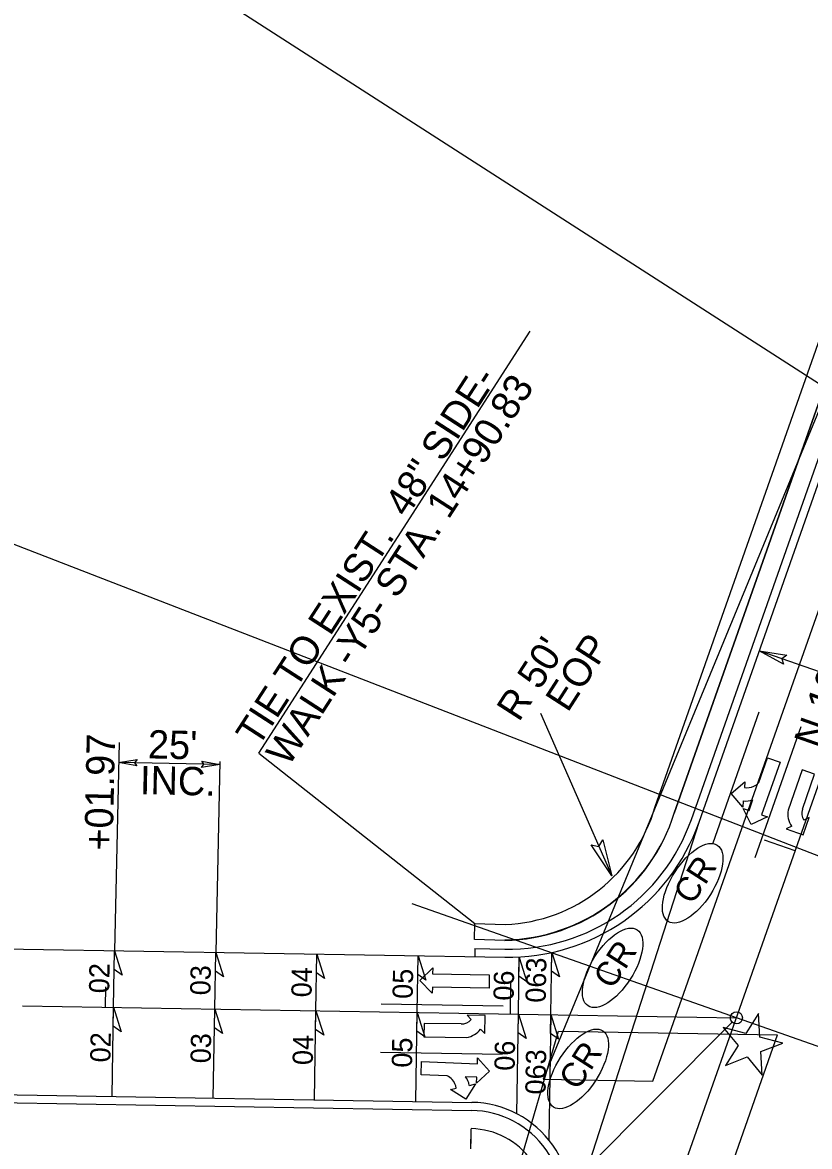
# Model space of a CAD drawing. Extents: x 1974386 to 1979988, y 776712 to 784860.
# Drawn here: x 1977201.1 to 1977395.6, y 780817.6 to 781095.4 of the extents above; entities that cross this region are included whole.
import ezdxf

# ---------------------------------------------------------------- set-up
doc = ezdxf.new("R2010")
doc.units = 0
for name, color, linetype in [('Prop Conc 2ft 6in Curb and Gutter', 7, 'Continuous'), ('Prop Conc 4in Sidewalk', 7, 'Continuous'), ('Prop Conc 5in Monolithic Keyed In Island', 7, 'Continuous'), ('Prop Dimension', 7, 'Continuous'), ('Prop Dimension Text', 7, 'Continuous'), ('Prop EOT', 7, 'Continuous'), ('Prop Horizontal Alignment', 7, 'Continuous'), ('Prop Horizontal Alignment Direction Label', 7, 'Continuous'), ('Prop Horizontal Alignment Station Label', 7, 'Continuous'), ('Prop Horizontal Alignment Tick Large', 7, 'Continuous'), ('Prop Horizontal Alignment Tick Small', 7, 'Continuous'), ('Prop Lane Arrow CELL', 7, 'Continuous'), ('Prop Lane Lines', 7, 'Continuous'), ('Prop RDY Traffic Signal CELL', 7, 'Continuous'), ('Prop Superelevation  Arrow CELL', 7, 'Continuous'), ('Prop Superelevation Label', 7, 'Continuous'), ('Prop Terminator CELL', 7, 'Continuous'), ('Prop WCC CELL', 7, 'Continuous'), ('Scratch_Level_1', 7, 'Continuous'), ('Scratch_Level_2', 7, 'Continuous'), ('Scratch_Level_3', 7, 'Continuous'), ('Sheet Layout Plan Border', 7, 'Continuous')]:
    doc.layers.add(name, color=color, linetype=linetype)

msp = doc.modelspace()

# ---------------------------------------------------------------- linework, layer by layer
at = {"layer": 'Prop Conc 2ft 6in Curb and Gutter'}
for p, q in [((1977366.39, 780898.48), (1977431.87, 781084.7)), ((1977312.89, 780866.54), (1977312.86, 780864.54)), ((1977312.89, 780866.54), (1977320.3, 780866.41)), ((1977159.54, 780829.11), (1977312.1, 780826.54))]:
    msp.add_line(p, q, dxfattribs=at)
for centre, radius, start, end in [((1977321.11, 780914.4), 48, 269.0355, 340.6265), ((1977311.71, 780803.55), 23, 341.3426, 89.0355)]:
    msp.add_arc(centre, radius, start, end, dxfattribs=at)
at = {"layer": 'Prop Conc 4in Sidewalk'}
for p, q in [((1977357.43, 780901.63), (1977422.91, 781087.85)), ((1977357.43, 780901.63), (1977422.91, 781087.85)), ((1977362.15, 780899.97), (1977427.63, 781086.19)), ((1977427.63, 781086.19), (1977362.15, 780899.97)), ((1977312.81, 780868.8), (1977312.88, 780872.74)), ((1977312.88, 780872.74), (1977320.41, 780872.49)), ((1977320.34, 780868.55), (1977312.81, 780868.8)), ((1977311.94, 780817.04), (1977312.02, 780822.04)), ((1977311.98, 780819.54), (1977312.02, 780822.04)), ((1977311.94, 780817.04), (1977311.98, 780819.54))]:
    msp.add_line(p, q, dxfattribs=at)
for centre, radius, start, end in [((1977319.57, 780913.33), 44.63, 270.9928, 342.5837), ((1977319.46, 780913.25), 44.71, 271.1306, 342.7215), ((1977318.71, 780912.73), 40.28, 272.4111, 344.002), ((1977311.71, 780803.55), 18.5, 341.3426, 89.0355)]:
    msp.add_arc(centre, radius, start, end, dxfattribs=at)
at = {"layer": 'Prop Conc 5in Monolithic Keyed In Island'}
msp.add_line((1977297.32, 780877.65), (1977457.7, 780821.25), dxfattribs=at)
at = {"layer": 'Prop Dimension'}
for p, q in [((1977259.55, 780914.86), (1977326.6, 781019.14)), ((1977441.18, 780919.75), (1977383.17, 780940.15)), ((1977329.14, 780924.69), (1977346.72, 780884.53)), ((1977225, 780917.45), (1977223.89, 780866.03)), ((1977259.55, 780914.86), (1977312.88, 780872.74)), ((1977249.89, 780912), (1977224.9, 780912.54)), ((1977249.91, 780912.77), (1977248.89, 780865.61))]:
    msp.add_line(p, q, dxfattribs=at)
at = {"layer": 'Prop EOT'}
for p, q in [((1977368.28, 780897.82), (1977433.76, 781084.03)), ((1977009.95, 780869.54), (1977201.38, 780866.41)), ((1977201.38, 780866.41), (1977320.27, 780864.41)), ((1977159.58, 780831.11), (1977312.13, 780828.54))]:
    msp.add_line(p, q, dxfattribs=at)
for centre, radius, start, end in [((1977321.11, 780914.4), 50, 269.0355, 340.6265), ((1977311.71, 780803.55), 25, 341.3426, 89.0355)]:
    msp.add_arc(centre, radius, start, end, dxfattribs=at)
at = {"layer": 'Prop Horizontal Alignment'}
for p, q in [((1977307.82, 780651.27), (1977457.11, 781075.82)), ((1977201.14, 780852.41), (1977377.51, 780849.45)), ((1977201.14, 780852.41), (1977377.51, 780849.45))]:
    msp.add_line(p, q, dxfattribs=at)
at = {"layer": 'Prop Horizontal Alignment Station Label'}
msp.add_line((1977376.45, 780848.38), (1977216.45, 780687.69), dxfattribs=at)
msp.add_circle((1977377.51, 780849.45), 1.5, dxfattribs=at)
msp.add_circle((1977377.51, 780849.45), 1.5, dxfattribs=at)
at = {"layer": 'Prop Horizontal Alignment Tick Large'}
for p, q in [((1977392.01, 780890.69), (1977384.46, 780893.35)), ((1977321.67, 780850.39), (1977321.81, 780858.38))]:
    msp.add_line(p, q, dxfattribs=at)
at = {"layer": 'Prop Horizontal Alignment Tick Small'}
msp.add_line((1977221.69, 780852.07), (1977221.77, 780857.07), dxfattribs=at)
at = {"layer": 'Prop Lane Arrow CELL'}
for p, q in [((1977383.05, 780907.62), (1977385.18, 780913.71)), ((1977385.18, 780913.71), (1977388.3, 780912.62)), ((1977388.3, 780912.62), (1977383.74, 780899.59)), ((1977393.72, 780910.72), (1977390.3, 780900.73)), ((1977396.84, 780909.65), (1977393.72, 780910.72)), ((1977376.21, 780904.87), (1977379.56, 780907.78)), ((1977379.56, 780907.78), (1977379.48, 780906.33)), ((1977393.88, 780900.99), (1977396.84, 780909.65)), ((1977379.12, 780901.52), (1977376.21, 780904.87)), ((1977379.22, 780903.02), (1977379.12, 780901.52)), ((1977380.63, 780900.68), (1977381.57, 780903.37)), ((1977381.16, 780897.21), (1977379.21, 780901.17)), ((1977379.21, 780901.17), (1977380.63, 780900.68)), ((1977383.74, 780899.59), (1977385.16, 780899.1)), ((1977385.16, 780899.1), (1977381.16, 780897.21)), ((1977391.17, 780896.79), (1977389.84, 780896.14)), ((1977393.98, 780894.66), (1977395.49, 780898.91)), ((1977395.49, 780898.91), (1977394.16, 780898.25)), ((1977389.84, 780896.14), (1977393.98, 780894.66)), ((1977299.29, 780858.66), (1977302.5, 780861.79)), ((1977302.5, 780861.79), (1977302.47, 780860.3)), ((1977302.38, 780855.5), (1977299.29, 780858.66)), ((1977302.47, 780860.3), (1977316.47, 780860.03)), ((1977316.47, 780860.03), (1977316.41, 780856.73)), ((1977302.41, 780857), (1977302.38, 780855.5)), ((1977316.41, 780856.73), (1977302.41, 780857)), ((1977315.47, 780850), (1977310.97, 780850.1)), ((1977310.97, 780850.1), (1977312.01, 780849.04)), ((1977315.37, 780845.6), (1977315.47, 780850)), ((1977300.34, 780848.02), (1977300.31, 780844.72)), ((1977309.49, 780847.92), (1977300.34, 780848.02)), ((1977314.33, 780846.66), (1977315.37, 780845.6)), ((1977300.31, 780844.72), (1977310.86, 780844.6)), ((1977299.6, 780835.35), (1977299.74, 780838.65)), ((1977299.74, 780838.65), (1977313.53, 780838.07)), ((1977313.53, 780838.07), (1977313.59, 780839.57)), ((1977313.59, 780839.57), (1977316.55, 780836.29)), ((1977316.55, 780836.29), (1977313.33, 780833.27)), ((1977306.04, 780835.08), (1977299.6, 780835.35)), ((1977313.39, 780834.77), (1977310.54, 780834.89)), ((1977313.02, 780833.09), (1977310.66, 780829.33)), ((1977311.55, 780832.75), (1977313.02, 780833.09)), ((1977313.33, 780833.27), (1977313.39, 780834.77)), ((1977306.9, 780831.69), (1977308.32, 780832.03)), ((1977310.66, 780829.33), (1977306.9, 780831.69))]:
    msp.add_line(p, q, dxfattribs=at)
for centre, radius, start, end in [((1977380.06, 780910.72), 4.43, 262.4428, 293.2964), ((1977380.96, 780909.03), 2.52, 289.8063, 326.1183), ((1977379.82, 780907.43), 4.43, 262.324, 293.2026), ((1977395.45, 780899.81), 5.25, 169.7805, 215.0922), ((1977396.96, 780899.93), 3.27, 161.1044, 210.7626), ((1977309.54, 780851.18), 3.27, 269.3608, 319.019), ((1977310.12, 780849.79), 5.25, 278.0369, 323.3486), ((1977305.3, 780832.66), 2.52, 36.676, 72.988), ((1977303.94, 780831.31), 4.43, 9.3125, 40.1661), ((1977307.16, 780832.04), 4.43, 9.1937, 40.0723)]:
    msp.add_arc(centre, radius, start, end, dxfattribs=at)
at = {"layer": 'Prop Lane Lines'}
for p, q in [((1977371.78, 780892.7), (1977383.16, 780925.07)), ((1977382.16, 780889.06), (1977393.54, 780921.42)), ((1977289.77, 780852.92), (1977319.93, 780852.41)), ((1977289.57, 780840.92), (1977319.73, 780840.42))]:
    msp.add_line(p, q, dxfattribs=at)
at = {"layer": 'Prop RDY Traffic Signal CELL'}
msp.add_lwpolyline([(1977377.92, 780842.57), (1977374.78, 780837.69), (1977380.19, 780839.79), (1977383.87, 780835.29), (1977383.54, 780841.1), (1977388.96, 780843.21), (1977383.34, 780844.68), (1977383.01, 780850.48), (1977379.86, 780845.6), (1977374.24, 780847.07), (1977377.92, 780842.57)], dxfattribs=at)
at = {"layer": 'Prop Superelevation  Arrow CELL'}
for p, q in [((1977223.66, 780852.04), (1977223.89, 780866.03)), ((1977248.65, 780851.61), (1977248.89, 780865.61)), ((1977273.65, 780851.19), (1977273.89, 780865.19)), ((1977298.65, 780850.77), (1977298.88, 780864.77)), ((1977323.64, 780850.35), (1977323.88, 780864.35)), ((1977331.67, 780850.22), (1977331.93, 780865.59)), ((1977223.29, 780830.04), (1977223.66, 780852.04)), ((1977248.28, 780829.62), (1977248.65, 780851.61)), ((1977273.28, 780829.2), (1977273.65, 780851.19)), ((1977298.28, 780828.78), (1977298.65, 780850.77)), ((1977323.23, 780825.73), (1977323.64, 780850.35)), ((1977331.67, 780850.22), (1977331.15, 780819.26))]:
    msp.add_line(p, q, dxfattribs=at)
for points in [[(1977223.89, 780866.03), (1977225.79, 780860), (1977223.82, 780861.41)], [(1977248.89, 780865.61), (1977250.79, 780859.58), (1977248.81, 780860.99)], [(1977273.89, 780865.19), (1977275.79, 780859.16), (1977273.81, 780860.57)], [(1977298.88, 780864.77), (1977300.78, 780858.74), (1977298.81, 780860.15)], [(1977323.88, 780864.35), (1977325.78, 780858.32), (1977323.8, 780859.73)], [(1977331.93, 780865.59), (1977333.83, 780859.56), (1977331.85, 780860.96)], [(1977223.66, 780852.04), (1977225.56, 780846), (1977223.58, 780847.41)], [(1977248.65, 780851.61), (1977250.55, 780845.58), (1977248.58, 780846.99)], [(1977273.65, 780851.19), (1977275.55, 780845.16), (1977273.57, 780846.57)], [(1977298.65, 780850.77), (1977300.55, 780844.74), (1977298.57, 780846.15)], [(1977323.64, 780850.35), (1977325.54, 780844.32), (1977323.57, 780845.73)], [(1977331.67, 780850.22), (1977333.57, 780844.18), (1977331.6, 780845.59)]]:
    msp.add_lwpolyline(points, close=True, dxfattribs=at)
at = {"layer": 'Prop Terminator CELL'}
for points in [[(1977389.15, 780936.82), (1977383.17, 780940.15), (1977389.97, 780939.03), (1977388.76, 780938.19)], [(1977229.38, 780911.67), (1977224.9, 780912.54), (1977229.44, 780913.24), (1977228.85, 780912.45)], [(1977245.41, 780912.87), (1977249.89, 780912), (1977245.35, 780911.3), (1977245.94, 780912.08)], [(1977344.53, 780893.4), (1977346.72, 780884.53), (1977341.63, 780892.18), (1977343.55, 780891.77)]]:
    msp.add_lwpolyline(points, close=True, dxfattribs=at)
at = {"layer": 'Prop WCC CELL'}
for centre in [(1977366.71, 780882.7), (1977346.93, 780861.79), (1977338.42, 780836.82)]:
    msp.add_ellipse(centre, major_axis=(6.07, 9.43), ratio=0.462467, dxfattribs=at)
at = {"layer": 'Scratch_Level_1'}
for p, q in [((1977516.04, 781286.37), (1977329.74, 780834.25)), ((1977356.9, 780833.79), (1977516.04, 781286.37)), ((1977329.74, 780834.25), (1977356.9, 780833.79))]:
    msp.add_line(p, q, dxfattribs=at)
at = {"layer": 'Scratch_Level_2'}
for p, q in [((1977203.85, 780401.24), (1977333.59, 780846.18)), ((1977318.2, 780647.62), (1977387.7, 780845.27)), ((1977333.59, 780846.18), (1977387.7, 780845.27))]:
    msp.add_line(p, q, dxfattribs=at)
at = {"layer": 'Scratch_Level_3'}
msp.add_line((1977335.4, 780795.55), (1977368.28, 780897.82), dxfattribs=at)
at = {"layer": 'Sheet Layout Plan Border'}
for points in [[(1977881.86, 780701.89), (1978387.67, 782007.32), (1977408.59, 782386.68), (1976902.78, 781081.25)], [(1977111.11, 779526.05), (1977868.38, 780703.57), (1976985.24, 781271.52), (1976227.97, 780094)]]:
    msp.add_lwpolyline(points, close=True, dxfattribs=at)

# ---------------------------------------------------------------- texts
at = {"layer": 'Prop Dimension Text'}
for s, rotation, p in [('TIE TO EXIST.  48" SIDE-', 57.0984, (1977259.37, 780916.08)), ('WALK -Y5- STA. 14+90.83', 57.0984, (1977266.82, 780911.26)), ("R 50'", 57.255, (1977323.78, 780922.34)), ('EOP', 57.255, (1977335.84, 780924.68)), ('+01.97', 88.7641, (1977223.41, 780890.69)), ("25'", 358.7641, (1977232.07, 780913.56)), ('INC.', 358.7641, (1977230.11, 780904.72))]:
    msp.add_text(s, height=7, rotation=rotation, dxfattribs=at).set_placement(p)
at = {"layer": 'Prop Horizontal Alignment Direction Label'}
msp.add_text('N 19%%d 22\' 24.7" E', height=7, rotation=70.6265, dxfattribs=at).set_placement((1977398.19, 780915.64))
at = {"layer": 'Prop Superelevation Label'}
for s, p in [('063', (1977330.4, 780853.14)), ('02', (1977222.56, 780855.47)), ('03', (1977247.56, 780854.97)), ('04', (1977272.55, 780854.47)), ('05', (1977297.55, 780854.09)), ('06', (1977322.48, 780853.65)), ('02', (1977222.86, 780838.39)), ('03', (1977247.65, 780838.17)), ('04', (1977272.86, 780837.73)), ('05', (1977297.36, 780837.09)), ('06', (1977322.72, 780836.33)), ('063', (1977330.35, 780830.46))]:
    msp.add_text(s, height=5, rotation=89.0355, dxfattribs=at).set_placement(p)
at = {"layer": 'Prop WCC CELL'}
for p in [(1977366.65, 780877.14), (1977346.87, 780856.23), (1977338.35, 780831.25)]:
    msp.add_text('CR', height=6, rotation=57.255, dxfattribs=at).set_placement(p)

doc.saveas('drawing.dxf')
